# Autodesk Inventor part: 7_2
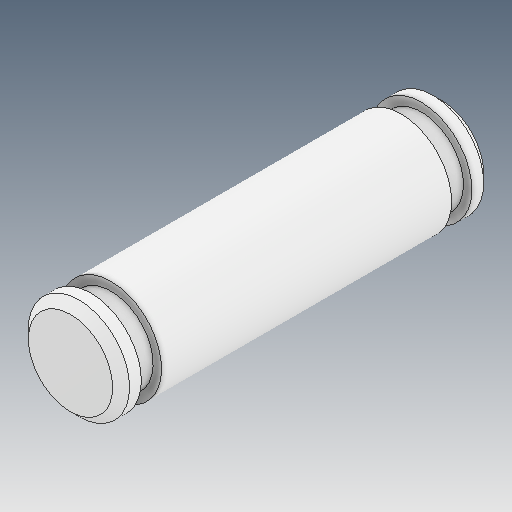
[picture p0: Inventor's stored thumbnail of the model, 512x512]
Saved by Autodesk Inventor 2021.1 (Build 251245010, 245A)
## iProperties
Created: 2021-06
Part Number: 7_2
Material: Ogólny
Document SubType Name: Modeling
Designer: user
Density: 1 g/cm^3
Appearance: Domyślna
Author: user
Revision Number: ÈÎºÎ
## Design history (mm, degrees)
feature "ÊäÈë1"
node "Bryła1"
